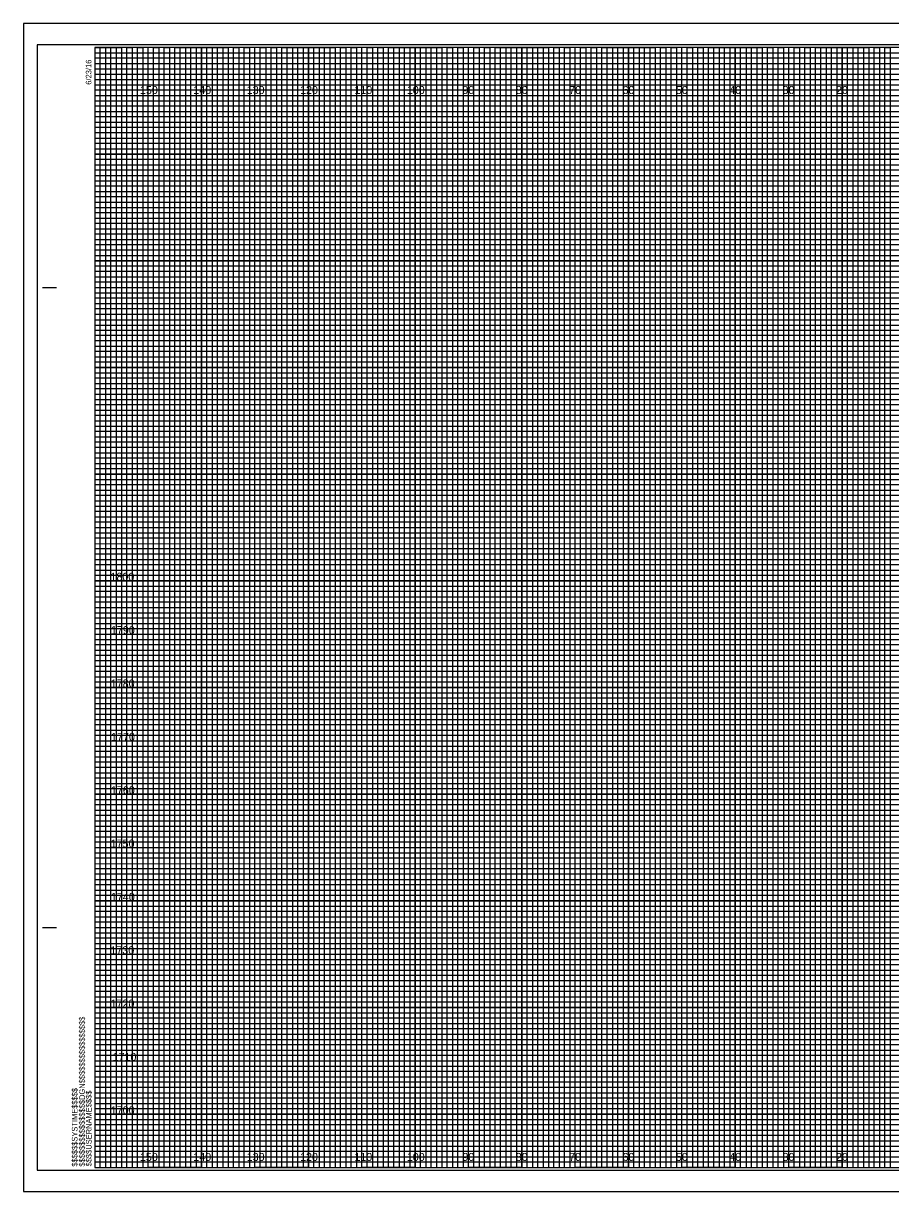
# Model space of a CAD drawing. Extents: x -3334 to 0, y 84 to 12624.
# Drawn here: x -1086.1 to -923.7, y 84.7 to 303.7 of the extents above; entities that cross this region are included whole.
import ezdxf

# ---------------------------------------------------------------- set-up
doc = ezdxf.new("R2010")
doc.units = 0
for name, color, linetype in [('Old_Level_62', 7, 'Continuous'), ('Pattern 1', 7, 'Continuous'), ('Pattern 18', 7, 'Continuous'), ('Pattern 4', 7, 'Continuous'), ('Pattern 5', 7, 'Continuous'), ('Prop Dimension', 7, 'Continuous'), ('Prop Horizontal Alignment', 7, 'Continuous'), ('Raster_Level_0', 7, 'Continuous'), ('Scratch_Level_0', 7, 'Continuous'), ('Scratch_Level_3', 7, 'Continuous'), ('Scratch_Level_5', 7, 'Continuous')]:
    doc.layers.add(name, color=color, linetype=linetype)

msp = doc.modelspace()

# ---------------------------------------------------------------- linework, layer by layer
at = {"layer": 'Old_Level_62'}
for p, q in [((-1082.55, 254.25), (-1080.05, 254.25)), ((-1082.45, 254.25), (-1079.95, 254.25)), ((-1082.55, 134.25), (-1080.05, 134.25)), ((-1082.45, 134.25), (-1079.95, 134.25)), ((-1072.75, 89.25), (-1072.75, 89.25)), ((-1072.75, 89.25), (-1072.75, 89.25)), ((-1072.75, 89.25), (-1072.75, 89.25)), ((-1072.75, 89.25), (-1072.75, 89.25)), ((-1072.75, 89.25), (-1072.75, 89.25)), ((-1072.75, 89.25), (-1072.75, 89.25)), ((-1072.75, 89.25), (-1072.75, 89.25))]:
    msp.add_line(p, q, dxfattribs=at)
msp.add_lwpolyline([(-752.75, 299.25), (-1072.75, 299.25), (-1072.75, 89.25), (-752.75, 89.25)], close=True, dxfattribs=at)
at = {"layer": 'Pattern 18'}
msp.add_lwpolyline([(-1086.15, 84.75), (-749.45, 84.75), (-749.45, 303.75), (-1086.15, 303.75)], close=True, dxfattribs=at)
at = {"layer": 'Pattern 4'}
for p, q in [((-1072.75, 298.25), (-812.75, 298.25)), ((-812.75, 297.23), (-1072.75, 297.23)), ((-1072.75, 297.23), (-1072.75, 296.25)), ((-1072.75, 296.25), (-812.75, 296.25)), ((-812.75, 295.14), (-1072.75, 295.14)), ((-1072.75, 295.14), (-1072.75, 293.25)), ((-1072.75, 293.25), (-752.75, 293.25))]:
    msp.add_line(p, q, dxfattribs=at)
for points in [[(-1072.75, 292.25), (-802.75, 292.25), (-752.75, 292.25), (-752.75, 291.25), (-1072.75, 291.25)], [(-1072.75, 290.25), (-752.75, 290.25), (-752.75, 288.25), (-1072.75, 288.25)], [(-1072.75, 287.25), (-752.75, 287.25), (-752.75, 286.25), (-1072.75, 286.23)], [(-1072.75, 285.25), (-752.75, 285.25), (-752.75, 283.25), (-1072.75, 283.25)], [(-1072.75, 282.25), (-752.75, 282.25), (-752.75, 281.25), (-1072.75, 281.25)], [(-1072.75, 280.25), (-752.75, 280.25), (-752.75, 278.25), (-1072.75, 278.25)], [(-1072.75, 277.25), (-752.75, 277.25), (-752.75, 276.25), (-1072.75, 276.25)], [(-1072.75, 275.25), (-752.75, 275.25), (-752.75, 273.25), (-1072.75, 273.25)], [(-1072.75, 272.25), (-752.75, 272.25), (-752.75, 271.25), (-1072.75, 271.25)], [(-1072.75, 270.25), (-752.75, 270.25), (-752.75, 268.25), (-1072.75, 268.25)], [(-1072.75, 267.25), (-752.75, 267.25), (-752.75, 266.25), (-1072.75, 266.25)], [(-1072.75, 265.25), (-752.75, 265.25), (-752.75, 263.2), (-752.75, 262.25), (-752.75, 261.25), (-1072.75, 261.25)], [(-1072.75, 263.25), (-752.75, 263.25), (-752.75, 262.25), (-1072.75, 262.25)], [(-1072.75, 260.25), (-752.75, 260.25), (-752.75, 258.25), (-1072.75, 258.28)], [(-1072.75, 258.28), (-752.75, 258.25), (-752.75, 257.25), (-1072.75, 257.25)], [(-1072.75, 256.25), (-752.75, 256.25), (-752.75, 255.25), (-1072.75, 255.25)], [(-1072.75, 253.25), (-752.75, 253.25), (-752.75, 252.25), (-1072.75, 252.25)], [(-1072.75, 251.25), (-752.75, 251.25), (-752.75, 250.25), (-1072.75, 250.25)], [(-1072.82, 248.14), (-752.75, 248.14), (-752.75, 247.13), (-1072.82, 247.13)], [(-1072.75, 246.25), (-752.75, 246.25), (-752.75, 245.25), (-1072.75, 245.25)], [(-1072.75, 243.25), (-752.75, 243.25), (-752.75, 242.25), (-1072.75, 242.25)], [(-1072.75, 241.25), (-752.75, 241.25), (-752.75, 240.25), (-1072.75, 240.25)], [(-1072.75, 238.25), (-752.75, 238.25), (-752.75, 237.25), (-1072.75, 237.25)], [(-1072.75, 236.25), (-752.75, 236.25), (-752.75, 235.25), (-1072.75, 235.25)], [(-1072.75, 233.25), (-752.75, 233.25), (-752.75, 232.25), (-1072.75, 232.25)], [(-1072.75, 231.25), (-752.75, 231.25), (-752.75, 230.25), (-1072.75, 230.25)], [(-1072.75, 228.25), (-752.75, 228.25), (-752.76, 227.23), (-1072.75, 227.25)], [(-1072.75, 226.25), (-752.75, 226.25), (-752.75, 225.25), (-1072.75, 225.25)], [(-1072.75, 223.25), (-752.75, 223.25), (-752.75, 222.25), (-1072.75, 222.25)], [(-1072.75, 221.25), (-752.75, 221.25), (-752.75, 220.25), (-1072.75, 220.25)], [(-1072.75, 218.25), (-752.75, 218.25), (-752.75, 217.25), (-1072.75, 217.25)], [(-1072.75, 216.25), (-752.75, 216.25), (-752.75, 215.25), (-1072.75, 215.25)], [(-1072.75, 213.25), (-752.75, 213.25), (-752.75, 212.25), (-1072.75, 212.25)], [(-1072.75, 211.25), (-752.75, 211.25), (-752.75, 210.25), (-1072.75, 210.25)], [(-1072.75, 208.25), (-752.75, 208.25), (-752.75, 207.25), (-1072.75, 207.25)], [(-1072.75, 206.24), (-752.68, 206.16), (-752.75, 205.25), (-1072.75, 205.25)], [(-1072.75, 203.25), (-752.75, 203.25), (-752.75, 202.25), (-1072.75, 202.25)], [(-1072.75, 201.25), (-752.75, 201.25), (-752.75, 200.25), (-1072.75, 200.25)], [(-1072.75, 198.25), (-752.75, 198.25), (-752.75, 197.25), (-1072.75, 197.25)], [(-1072.75, 196.25), (-752.75, 196.25), (-752.75, 195.25), (-1072.75, 195.25)], [(-1072.75, 193.25), (-752.75, 193.25), (-752.75, 192.25), (-1072.75, 192.25)], [(-1072.75, 191.25), (-752.75, 191.25), (-752.75, 190.25), (-1072.75, 190.25)], [(-1072.75, 188.25), (-752.75, 188.25), (-752.75, 187.25), (-1072.75, 187.25)], [(-1072.75, 186.25), (-752.75, 186.25), (-752.75, 185.25), (-1072.75, 185.25)], [(-1072.75, 183.25), (-752.75, 183.25), (-752.75, 182.25), (-1072.75, 182.25)], [(-1072.75, 181.25), (-752.75, 181.25), (-752.75, 180.25), (-1072.75, 180.25)], [(-1072.75, 178.25), (-752.75, 178.25), (-752.75, 177.25), (-1072.75, 177.25)], [(-1072.75, 176.25), (-752.75, 176.25), (-752.75, 175.25), (-1072.75, 175.25)], [(-1072.75, 173.25), (-752.75, 173.25), (-752.75, 172.25), (-1072.75, 172.25)], [(-1072.75, 171.25), (-752.75, 171.25), (-752.75, 170.25), (-1072.75, 170.25)], [(-1072.75, 168.25), (-752.75, 168.25), (-752.76, 167.23), (-1072.75, 167.25)], [(-1072.75, 166.25), (-752.75, 166.25), (-752.75, 165.25), (-1072.75, 165.25)], [(-1072.75, 163.25), (-752.75, 163.25), (-752.75, 162.25), (-1072.75, 162.25)], [(-1072.75, 161.25), (-752.75, 161.25), (-752.75, 160.25), (-1072.75, 160.25)], [(-1072.75, 158.25), (-752.75, 158.25), (-752.75, 157.25), (-1072.75, 157.25)], [(-1072.75, 156.25), (-752.75, 156.25), (-752.75, 155.25), (-1072.75, 155.25)], [(-1072.75, 153.25), (-752.75, 153.25), (-752.75, 152.25), (-1072.75, 152.25)], [(-1072.75, 151.25), (-752.75, 151.25), (-752.75, 150.25), (-1072.75, 150.25)], [(-1072.75, 148.25), (-752.75, 148.25), (-752.75, 147.25), (-1072.75, 147.25)], [(-1072.75, 146.24), (-752.68, 146.16), (-752.75, 145.25), (-1072.75, 145.25)], [(-1072.75, 143.25), (-752.75, 143.25), (-752.75, 142.25), (-1072.75, 142.25)], [(-1072.75, 141.25), (-752.75, 141.25), (-752.75, 140.25), (-1072.75, 140.25)], [(-1072.75, 138.25), (-752.75, 138.25), (-752.75, 137.25), (-1072.75, 137.25)], [(-1072.75, 136.25), (-752.75, 136.25), (-752.75, 135.25), (-1072.75, 135.25)], [(-1072.75, 133.25), (-752.75, 133.25), (-752.75, 132.25), (-1072.75, 132.25)], [(-1072.75, 131.25), (-752.75, 131.25), (-752.75, 130.25), (-1072.75, 130.25)], [(-1072.75, 128.25), (-752.75, 128.25), (-752.75, 127.25), (-1072.75, 127.25)], [(-1072.75, 126.25), (-752.75, 126.25), (-752.75, 125.25), (-1072.75, 125.25)], [(-1072.75, 123.25), (-752.75, 123.25), (-752.75, 122.25), (-1072.75, 122.25)], [(-1072.75, 121.25), (-752.75, 121.25), (-752.75, 120.25), (-1072.75, 120.25)], [(-1072.75, 118.25), (-752.75, 118.25), (-752.75, 117.25), (-1072.75, 117.25)], [(-1072.75, 116.25), (-752.75, 116.25), (-752.75, 115.25), (-1072.75, 115.25)], [(-1072.75, 113.25), (-752.75, 113.25), (-752.75, 112.25), (-1072.75, 112.25)], [(-1072.75, 111.25), (-752.75, 111.25), (-752.75, 110.25), (-1072.75, 110.25)], [(-1072.75, 108.25), (-752.75, 108.25), (-752.75, 107.25), (-1072.75, 107.25)], [(-1072.75, 106.25), (-752.75, 106.25), (-752.75, 105.25), (-1072.75, 105.25)], [(-1072.75, 103.25), (-752.75, 103.25), (-752.75, 102.25), (-1072.75, 102.25)], [(-1072.75, 101.25), (-752.75, 101.25), (-752.75, 100.25), (-1072.75, 100.25)], [(-1072.75, 98.25), (-752.75, 98.25), (-752.75, 97.25), (-1072.75, 97.25)], [(-1072.75, 96.25), (-752.75, 96.25), (-752.75, 95.25), (-1072.75, 95.25)], [(-1072.75, 93.25), (-752.75, 93.25), (-752.75, 92.25), (-1072.75, 92.25)], [(-1072.75, 91.25), (-752.75, 91.25), (-752.75, 90.25), (-1072.75, 90.25)]]:
    msp.add_lwpolyline(points, dxfattribs=at)
at = {"layer": 'Pattern 5'}
for p, q in [((-749.45, 303.75), (-1086.15, 303.75)), ((-1086.15, 303.75), (-1086.15, 84.75)), ((-1086.15, 84.75), (-749.45, 84.75))]:
    msp.add_line(p, q, dxfattribs=at)
at = {"layer": 'Prop Dimension'}
for points in [[(-1072.75, 89.25), (-1071.75, 89.25), (-1071.75, 299.25), (-1070.75, 299.25), (-1070.75, 89.25)], [(-1070.75, 89.25), (-1069.75, 89.25), (-1069.75, 299.25), (-1068.75, 299.25), (-1068.75, 89.25)], [(-1067.75, 89.25), (-1066.75, 89.25), (-1066.75, 299.25), (-1065.75, 299.25), (-1065.75, 89.25)], [(-1065.75, 89.25), (-1064.75, 89.25), (-1064.75, 299.25), (-1063.75, 299.25), (-1063.75, 89.25)], [(-1062.75, 89.25), (-1061.75, 89.25), (-1061.75, 299.25), (-1060.75, 299.25), (-1060.75, 89.25)], [(-1060.75, 89.25), (-1059.75, 89.25), (-1059.75, 299.25), (-1058.75, 299.25), (-1058.75, 89.25)], [(-1057.75, 89.25), (-1056.75, 89.25), (-1056.75, 299.25), (-1055.75, 299.25), (-1055.75, 89.25)], [(-1055.75, 89.25), (-1054.75, 89.25), (-1054.75, 299.25), (-1053.75, 299.25), (-1053.75, 89.25)], [(-1052.75, 89.25), (-1051.75, 89.25), (-1051.75, 299.25), (-1050.75, 299.25), (-1050.75, 89.25)], [(-1050.75, 89.25), (-1049.75, 89.25), (-1049.75, 299.25), (-1048.75, 299.25), (-1048.75, 89.25)], [(-1047.75, 89.25), (-1046.75, 89.25), (-1046.75, 299.25), (-1045.75, 299.25), (-1045.75, 89.25)], [(-1045.75, 89.25), (-1044.75, 89.25), (-1044.75, 299.25), (-1043.75, 299.25), (-1043.75, 89.25)], [(-1042.75, 89.25), (-1041.75, 89.25), (-1041.75, 299.25), (-1040.75, 299.25), (-1040.75, 89.25)], [(-1040.75, 89.25), (-1039.75, 89.25), (-1039.75, 299.25), (-1038.75, 299.25), (-1038.75, 89.25)], [(-1037.75, 89.25), (-1036.75, 89.25), (-1036.75, 299.25), (-1035.75, 299.25), (-1035.75, 89.25)], [(-1035.75, 89.25), (-1034.75, 89.25), (-1034.75, 299.25), (-1033.75, 299.25), (-1033.75, 89.25)], [(-1032.75, 89.25), (-1031.75, 89.25), (-1031.75, 299.25), (-1030.75, 299.25), (-1030.75, 89.25)], [(-1030.75, 89.25), (-1029.75, 89.25), (-1029.75, 299.25), (-1028.75, 299.25), (-1028.75, 89.25)], [(-1027.75, 89.25), (-1026.75, 89.25), (-1026.75, 299.25), (-1025.75, 299.25), (-1025.75, 89.25)], [(-1025.75, 89.25), (-1024.75, 89.25), (-1024.75, 299.25), (-1023.75, 299.25), (-1023.75, 89.25)], [(-1022.75, 89.25), (-1021.75, 89.25), (-1021.75, 299.25), (-1020.75, 299.25), (-1020.75, 89.25)], [(-1020.75, 89.25), (-1019.75, 89.25), (-1019.75, 299.25), (-1018.75, 299.25), (-1018.75, 89.25)], [(-1017.75, 89.25), (-1016.75, 89.25), (-1016.75, 299.25), (-1015.75, 299.25), (-1015.75, 89.25)], [(-1015.75, 89.25), (-1014.75, 89.25), (-1014.75, 299.25), (-1013.75, 299.25), (-1013.75, 89.25)], [(-1012.75, 89.25), (-1011.75, 89.25), (-1011.75, 299.25), (-1010.75, 299.25), (-1010.75, 89.25)], [(-1010.75, 89.25), (-1009.75, 89.25), (-1009.75, 299.25), (-1008.75, 299.25), (-1008.75, 89.25)], [(-1007.75, 89.25), (-1006.75, 89.25), (-1006.75, 299.25), (-1005.75, 299.25), (-1005.75, 89.25)], [(-1005.75, 89.25), (-1004.75, 89.25), (-1004.75, 299.25), (-1003.75, 299.25), (-1003.75, 89.25)], [(-1002.75, 89.25), (-1001.75, 89.25), (-1001.75, 299.25), (-1000.75, 299.25), (-1000.75, 89.25)], [(-1000.75, 89.25), (-999.75, 89.25), (-999.75, 299.25), (-998.75, 299.25), (-998.75, 89.25)], [(-997.75, 89.25), (-996.75, 89.25), (-996.75, 299.25), (-995.75, 299.25), (-995.75, 89.25)], [(-995.75, 89.25), (-994.75, 89.25), (-994.75, 299.25), (-993.75, 299.25), (-993.75, 89.25)], [(-992.75, 89.25), (-991.75, 89.25), (-991.75, 299.25), (-990.75, 299.25), (-990.75, 89.25)], [(-990.75, 89.25), (-989.75, 89.25), (-989.75, 299.25), (-988.75, 299.25), (-988.75, 89.25)], [(-987.75, 89.25), (-986.75, 89.25), (-986.75, 299.25), (-985.75, 299.25), (-985.75, 89.25)], [(-985.75, 89.25), (-984.75, 89.25), (-984.75, 299.25), (-983.75, 299.25), (-983.75, 89.25)], [(-982.75, 89.25), (-981.75, 89.25), (-981.75, 299.25), (-980.75, 299.25), (-980.75, 89.25)], [(-980.75, 89.25), (-979.75, 89.25), (-979.75, 299.25), (-978.75, 299.25), (-978.75, 89.25)], [(-977.75, 89.25), (-976.75, 89.25), (-976.75, 299.25), (-975.75, 299.25), (-975.75, 89.25)], [(-975.75, 89.25), (-974.75, 89.25), (-974.75, 299.25), (-973.75, 299.25), (-973.75, 89.25)], [(-972.75, 89.25), (-971.75, 89.25), (-971.75, 299.25), (-970.75, 299.25), (-970.75, 89.25)], [(-970.75, 89.25), (-969.75, 89.25), (-969.75, 299.25), (-968.75, 299.25), (-968.75, 89.25)], [(-967.75, 89.25), (-966.75, 89.25), (-966.75, 299.25), (-965.75, 299.25), (-965.75, 89.25)], [(-965.75, 89.25), (-964.75, 89.25), (-964.75, 299.25), (-963.75, 299.25), (-963.75, 89.25)], [(-962.75, 89.25), (-961.75, 89.25), (-961.75, 299.25), (-960.75, 299.25), (-960.75, 89.25)], [(-960.75, 89.25), (-959.75, 89.25), (-959.75, 299.25), (-958.75, 299.25), (-958.75, 89.25)], [(-957.75, 89.25), (-956.75, 89.25), (-956.75, 299.25), (-955.75, 299.25), (-955.75, 89.25)], [(-955.75, 89.25), (-954.75, 89.25), (-954.75, 299.25), (-953.75, 299.25), (-953.75, 89.25)], [(-952.75, 89.25), (-951.75, 89.25), (-951.75, 299.25), (-950.75, 299.25), (-950.75, 89.25)], [(-950.75, 89.25), (-949.75, 89.25), (-949.75, 299.25), (-948.75, 299.25), (-948.75, 89.25)], [(-947.75, 89.25), (-946.75, 89.25), (-946.75, 299.25), (-945.75, 299.25), (-945.75, 89.25)], [(-945.75, 89.25), (-944.75, 89.25), (-944.75, 299.25), (-943.75, 299.25), (-943.75, 89.25)], [(-942.75, 89.25), (-941.75, 89.25), (-941.75, 299.25), (-940.75, 299.25), (-940.75, 89.25)], [(-940.75, 89.25), (-939.75, 89.25), (-939.75, 299.25), (-938.75, 299.25), (-938.75, 89.25)], [(-937.75, 89.25), (-936.75, 89.25), (-936.75, 299.25), (-935.75, 299.25), (-935.75, 89.25)], [(-935.75, 89.25), (-934.75, 89.25), (-934.75, 299.25), (-933.75, 299.25), (-933.75, 89.25)], [(-932.75, 89.25), (-931.75, 89.25), (-931.75, 299.25), (-930.75, 299.25), (-930.75, 89.25)], [(-930.75, 89.25), (-929.75, 89.25), (-929.75, 299.25), (-928.75, 299.25), (-928.75, 89.25)], [(-927.75, 89.25), (-926.75, 89.25), (-926.75, 299.25), (-925.75, 299.25), (-925.75, 89.25)], [(-925.75, 89.25), (-924.75, 89.25), (-924.75, 299.25), (-923.75, 299.25), (-923.75, 89.25)]]:
    msp.add_lwpolyline(points, dxfattribs=at)
at = {"layer": 'Prop Horizontal Alignment'}
for points in [[(-1072.75, 299.25), (-1067.75, 299.25), (-1067.75, 89.25), (-1057.75, 89.25), (-1057.75, 299.25), (-1047.75, 299.25), (-1047.75, 89.25), (-1037.75, 89.25), (-1037.75, 299.25), (-1027.75, 299.25), (-1027.75, 89.25), (-1017.75, 89.25), (-1017.75, 299.25), (-1007.75, 299.25), (-1007.75, 89.25), (-997.75, 89.25), (-997.75, 299.25), (-987.75, 299.25), (-987.75, 89.25), (-977.75, 89.25), (-977.75, 299.25), (-967.75, 299.25), (-967.75, 89.25), (-957.75, 89.25), (-957.75, 299.25), (-947.75, 299.25), (-947.75, 89.25), (-937.75, 89.25), (-937.75, 299.25), (-927.75, 299.25), (-927.75, 89.25), (-917.75, 89.25)], [(-1072.75, 294.25), (-797.75, 294.25)], [(-1072.75, 274.25), (-752.75, 274.25), (-752.75, 284.25), (-1072.75, 284.25)], [(-1072.75, 254.25), (-752.75, 254.25), (-752.75, 264.25), (-1072.75, 264.25)], [(-1072.75, 234.25), (-752.75, 234.25), (-752.75, 244.25), (-1072.75, 244.25)], [(-1072.75, 214.25), (-752.75, 214.25), (-752.75, 224.25), (-1072.75, 224.25)], [(-1072.75, 194.25), (-752.75, 194.25), (-752.75, 204.25), (-1072.75, 204.25)], [(-1072.75, 174.25), (-752.75, 174.25), (-752.75, 184.25), (-1072.75, 184.25)], [(-1072.75, 154.25), (-752.75, 154.25), (-752.75, 164.25), (-1072.75, 164.25)], [(-1072.75, 134.25), (-752.75, 134.25), (-752.75, 144.25), (-1072.75, 144.25)], [(-1072.75, 114.25), (-752.75, 114.25), (-752.75, 124.25), (-1072.75, 124.25)], [(-1072.75, 94.25), (-752.75, 94.25), (-752.75, 104.25), (-1072.75, 104.25)]]:
    msp.add_lwpolyline(points, dxfattribs=at)
at = {"layer": 'Scratch_Level_0'}
for p, q in [((-1062.75, 89.25), (-1062.75, 299.25)), ((-1052.75, 89.25), (-1052.75, 299.25)), ((-1042.75, 89.25), (-1042.75, 299.25)), ((-1032.75, 89.25), (-1032.75, 299.25)), ((-1022.75, 89.25), (-1022.75, 299.25)), ((-1012.75, 89.25), (-1012.75, 299.25)), ((-1002.75, 89.25), (-1002.75, 299.25)), ((-992.75, 89.25), (-992.75, 299.25)), ((-982.75, 89.25), (-982.75, 299.25)), ((-972.75, 89.25), (-972.75, 299.25)), ((-962.75, 89.25), (-962.75, 299.25)), ((-952.75, 89.25), (-952.75, 299.25)), ((-942.75, 89.25), (-942.75, 299.25)), ((-932.75, 89.25), (-932.75, 299.25)), ((-1072.75, 289.25), (-752.75, 289.25)), ((-1072.75, 279.25), (-752.75, 279.25)), ((-1072.75, 269.25), (-752.75, 269.25)), ((-1072.75, 259.25), (-752.75, 259.25)), ((-1072.75, 249.25), (-752.75, 249.25)), ((-1072.75, 239.25), (-752.75, 239.25)), ((-1072.75, 229.25), (-752.75, 229.25)), ((-1072.75, 219.25), (-752.75, 219.25)), ((-1072.75, 209.25), (-752.75, 209.25)), ((-1072.75, 199.25), (-752.75, 199.25)), ((-1072.75, 189.25), (-752.75, 189.25)), ((-1072.75, 179.25), (-752.75, 179.25)), ((-1072.75, 169.25), (-752.75, 169.25)), ((-1072.75, 159.25), (-752.75, 159.25)), ((-1072.75, 149.25), (-752.75, 149.25)), ((-1072.75, 139.25), (-752.75, 139.25)), ((-1072.75, 129.25), (-752.75, 129.25)), ((-1072.75, 119.25), (-752.75, 119.25)), ((-1072.75, 109.25), (-752.75, 109.25)), ((-1072.75, 99.25), (-752.75, 99.25))]:
    msp.add_line(p, q, dxfattribs=at)
at = {"layer": 'Scratch_Level_3'}
for p, q in [((-1062.75, 299.25), (-1072.75, 299.25)), ((-1062.75, 89.25), (-1062.75, 299.25)), ((-1042.75, 299.25), (-1052.75, 299.25)), ((-1052.75, 299.25), (-1052.75, 89.25)), ((-1042.75, 89.25), (-1042.75, 299.25)), ((-1022.75, 299.25), (-1032.75, 299.25)), ((-1032.75, 299.25), (-1032.75, 89.25)), ((-1022.75, 89.25), (-1022.75, 299.25)), ((-1002.75, 299.25), (-1012.75, 299.25)), ((-1012.75, 299.25), (-1012.75, 89.25)), ((-1002.75, 89.25), (-1002.75, 299.25)), ((-982.75, 299.25), (-992.75, 299.25)), ((-992.75, 299.25), (-992.75, 89.25)), ((-982.75, 89.25), (-982.75, 299.25)), ((-962.75, 299.25), (-972.75, 299.25)), ((-972.75, 299.25), (-972.75, 89.25)), ((-962.75, 89.25), (-962.75, 299.25)), ((-942.75, 299.25), (-952.75, 299.25)), ((-952.75, 299.25), (-952.75, 89.25)), ((-942.75, 89.25), (-942.75, 299.25)), ((-922.75, 299.25), (-932.75, 299.25)), ((-932.75, 299.25), (-932.75, 89.25)), ((-1052.75, 89.25), (-1062.75, 89.25)), ((-1032.75, 89.25), (-1042.75, 89.25)), ((-1012.75, 89.25), (-1022.75, 89.25)), ((-992.75, 89.25), (-1002.75, 89.25)), ((-972.75, 89.25), (-982.75, 89.25)), ((-952.75, 89.25), (-962.75, 89.25)), ((-932.75, 89.25), (-942.75, 89.25))]:
    msp.add_line(p, q, dxfattribs=at)
for points in [[(-1072.75, 289.25), (-752.75, 289.25), (-752.75, 279.25), (-1072.75, 279.25)], [(-1072.75, 269.25), (-752.75, 269.25), (-752.75, 259.25), (-1072.75, 259.25)], [(-1072.75, 249.25), (-752.75, 249.25), (-752.75, 239.25), (-1072.75, 239.25)], [(-1072.75, 229.25), (-752.75, 229.25), (-752.75, 219.25), (-1072.75, 219.25)], [(-1072.75, 209.25), (-752.75, 209.25), (-752.75, 199.25), (-1072.75, 199.25)], [(-1072.75, 189.25), (-752.75, 189.25), (-752.75, 179.25), (-1072.75, 179.25)], [(-1072.75, 169.25), (-752.75, 169.25), (-752.75, 159.25), (-1072.75, 159.25)], [(-1072.75, 149.25), (-752.75, 149.25), (-752.75, 139.25), (-1072.75, 139.25)], [(-1072.75, 129.25), (-752.75, 129.25), (-752.75, 119.25), (-1072.75, 119.25)], [(-1072.75, 109.25), (-752.75, 109.25), (-752.75, 99.25), (-1072.75, 99.25)]]:
    msp.add_lwpolyline(points, dxfattribs=at)
at = {"layer": 'Scratch_Level_5'}
msp.add_lwpolyline([(-1083.55, 88.75), (-750.35, 88.75), (-750.35, 299.75), (-1083.55, 299.75)], close=True, dxfattribs=at)

# ---------------------------------------------------------------- texts
at = {"layer": 'Old_Level_62'}
for s, p in [('6/23/16', (-1073.4, 292.25)), ('$$$$$$$$$$$$$$$$DGN$$$$$$$$$$$$$$$$', (-1074.63, 89.43)), ('$$$$$$SYSTIME$$$$$', (-1076.01, 89.43)), ('$$$$USERNAME$$$$', (-1073.37, 89.48))]:
    msp.add_text(s, height=1.05, rotation=90, dxfattribs=at).set_placement(p)
at = {"layer": 'Pattern 1'}
for s, p in [('1800', (-1069.83, 199.25)), ('1790', (-1069.74, 189.25)), ('1780', (-1069.77, 179.25)), ('1770', (-1069.71, 169.25)), ('1760', (-1069.74, 159.25)), ('1750', (-1069.79, 149.25)), ('1740', (-1069.74, 139.25)), ('1730', (-1069.83, 129.25)), ('1720', (-1069.81, 119.25)), ('1710', (-1069.44, 109.25)), ('1700', (-1069.77, 99.25))]:
    msp.add_text(s, height=1.5, dxfattribs=at).set_placement(p)
at = {"layer": 'Raster_Level_0'}
for s, p in [('150', (-1064.3, 290.5)), ('140', (-1054.3, 290.5)), ('130', (-1044.3, 290.5)), ('120', (-1034.3, 290.5)), ('110', (-1024.12, 290.5)), ('100', (-1014.3, 290.5)), ('90', (-1003.89, 290.5)), ('80', (-993.89, 290.5)), ('70', (-983.89, 290.5)), ('60', (-973.89, 290.5)), ('50', (-963.89, 290.5)), ('40', (-953.89, 290.5)), ('30', (-943.89, 290.5)), ('20', (-933.89, 290.5)), ('150', (-1064.3, 90.5)), ('140', (-1054.3, 90.5)), ('130', (-1044.3, 90.5)), ('120', (-1034.3, 90.5)), ('110', (-1024.12, 90.5)), ('100', (-1014.3, 90.5)), ('90', (-1003.89, 90.5)), ('80', (-993.89, 90.5)), ('70', (-983.89, 90.5)), ('60', (-973.89, 90.5)), ('50', (-963.89, 90.5)), ('40', (-953.89, 90.5)), ('30', (-943.89, 90.5)), ('20', (-933.89, 90.5))]:
    msp.add_text(s, height=1.5, dxfattribs=at).set_placement(p)

doc.saveas('drawing.dxf')
